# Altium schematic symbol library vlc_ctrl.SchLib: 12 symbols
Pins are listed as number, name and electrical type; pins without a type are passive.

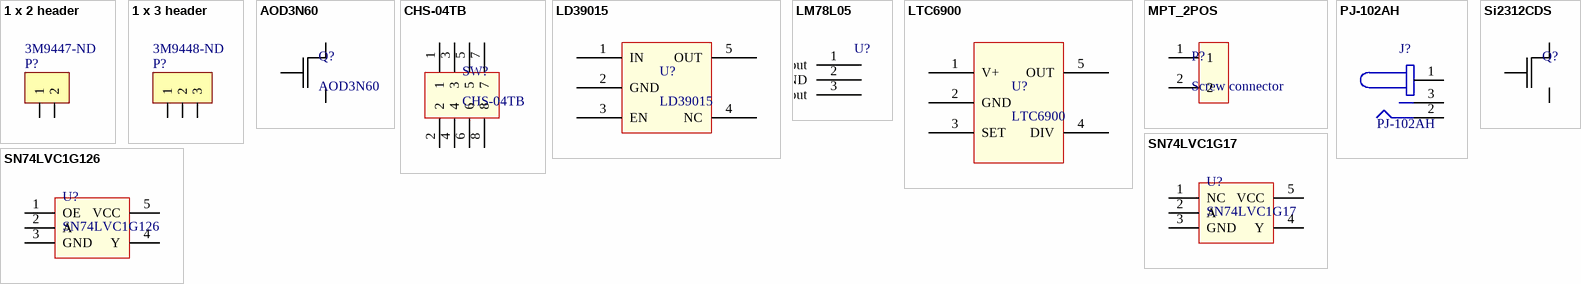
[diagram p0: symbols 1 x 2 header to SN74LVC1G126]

## 1 x 2 header
designator P?  Supplier Part Number 1: 3M9447-ND  (hidden comment: 1 x 2 header)
100 mils standard header
footprint 1x2 header (1x2 header, 100 mils)
pins: 1, 2

## 1 x 3 header
designator P?  Supplier Part Number 1: 3M9448-ND  (hidden comment: 1 x 3 header)
100 mils standard header
footprint 1x3 header (1x3 header, 100 mils)
pins: 1, 2, 3

## AOD3N60
designator Q?
600V,2.5A N-Channel MOSFET
footprint TO252 (TO252-3)
pins: 1 G, 3 S, 4 D

## CHS-04TB
designator SW?
SLIDE SWITCHES
footprint CHS04TB (4 POS DIP SWITCH)
pins: 1, 2, 3, 4, 5, 6, 7, 8

## LD39015
designator U?
150 mA low quiescent current and low noise voltage regulator
footprint SOT23-5 (SOT23, 5-Leads, Body 2.9x1.6mm, Pitch 0.95mm, Lead Span 2.8mm, IPC High Density)
pins: 1 IN, 2 GND, 3 EN, 4 NC, 5 OUT

## LM78L05
designator U?  (value not drawn)
LM78LXX Series 3-Terminal Positive Regulators
footprint TO92
pins: 1 Output, 2 GND, 3 Input

## LTC6900
designator U?
Low Power, 1kHz to 20MHz   Resistor Set SOT-23 Oscillator
footprint TSOT23
pins: 1 V+, 2 GND, 3 SET, 4 DIV, 5 OUT

## MPT_2POS
designator P?, comment Screw connector
Screw connector 2 positions
footprint MPT_2position (Screw connector 2 pos)
pins: 1, 2

## PJ-102AH
designator J?
CONN PWR JACK 2.1X5.5MM HIGH CUR
footprint PJ-102AH (Power Jack)
pins: 1, 2, 3

## Si2312CDS
designator Q?  (value not drawn)
N-Channel 20 V (D-S) MOSFET
footprint SOT95P250-3N (SOT23, 3-Leads, Body 2.9x1.3mm, Pitch 0.95mm, Lead Span 2.3mm, IPC Medium Density)
pins: 1 G, 2 S, 3 D

## SN74LVC1G17
designator U?
SINGLE SCHMITT-TRIGGER BUFFER
footprint SOT23-5 (SOT23, 5-Leads, Body 2.9x1.6mm, Pitch 0.95mm, Lead Span 2.8mm, IPC High Density)
pins: 1 NC, 2 A, 3 GND, 4 Y, 5 VCC

## SN74LVC1G126
designator U?
Single Bus Buffer Gate With 3-State Output
footprint SOT23-5 (SOT23, 5-Leads, Body 2.9x1.6mm, Pitch 0.95mm, Lead Span 2.8mm, IPC High Density)
pins: 1 OE, 2 A, 3 GND, 4 Y, 5 VCC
